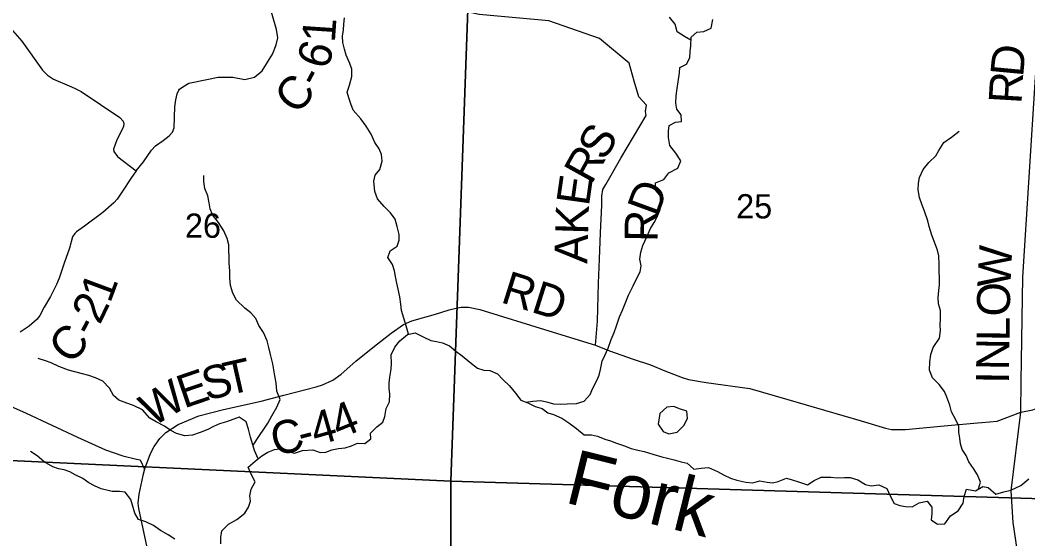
# Model space of a CAD drawing. Extents: x 2043100 to 2470832, y 443715 to 810583.
# Drawn here: x 2249519 to 2258688, y 675442 to 680160 of the extents above; entities that cross this region are included whole.
import ezdxf

# ---------------------------------------------------------------- set-up
doc = ezdxf.new("R2010")
doc.units = 0
for name, color, linetype in [('GM_X_County_Road', 7, 'Continuous'), ('GM_X_County_Road_Text', 7, 'Continuous'), ('GM_X_Minor_Lake', 7, 'Continuous'), ('GM_X_Minor_River', 7, 'Continuous'), ('GM_X_Minor_River_Text', 7, 'Continuous'), ('GM_X_Section', 7, 'Continuous'), ('GM_X_Section_Text', 7, 'Continuous'), ('GM_X_Township_Road', 7, 'Continuous'), ('GM_X_Township_Road_Text', 7, 'Continuous'), ('GM_X_Township_ROW', 7, 'Continuous')]:
    doc.layers.add(name, color=color, linetype=linetype)

msp = doc.modelspace()

# ---------------------------------------------------------------- linework, layer by layer
at = {"layer": 'GM_X_County_Road'}
for points in [[(2250963.1, 679521.8), (2250963.5, 679522.9), (2250967.9, 679532.7), (2250999.8, 679555), (2251053.7, 679585.4), (2251217.6, 679620.6), (2251321.7, 679641.4), (2251453.9, 679640.3), (2251562.2, 679619.1), (2251650.1, 679641.7), (2251721.8, 679700.3), (2251814.9, 679851.3), (2251848.3, 679935.7), (2251863.9, 679999.9), (2251851.3, 680075.9), (2251779.4, 680325.9)], [(2249449.9, 680065.1), (2249532.7, 679967.5), (2249720.8, 679706.3), (2249767.3, 679658.6), (2249821.6, 679622.9), (2249964.2, 679561.8), (2250014.5, 679540.1), (2250072.8, 679510.4), (2250425, 679274.5), (2250455.2, 679242.6), (2250463.4, 679218.6), (2250459.6, 679192.5), (2250394.5, 679061.8), (2250366.9, 678987.5), (2250371.1, 678965.5), (2250403.5, 678919.6), (2250405.4, 678918.2)], [(2250574.7, 678790.6), (2250640.2, 678871.2), (2250715.5, 678977.9), (2250751.3, 679018.3), (2250821.1, 679064.8), (2250874.8, 679107.3), (2250904.6, 679141.6), (2250920.4, 679181.7), (2250927, 679372.2), (2250934.6, 679436.3), (2250948.2, 679488.5), (2250963.1, 679521.8)], [(2250405.4, 678918.2), (2250407.7, 678916.5), (2250574.7, 678790.6), (2250527.1, 678720.1), (2250449.8, 678603.4), (2250402.3, 678532.9), (2250372.5, 678498.6), (2250271, 678409.7), (2250103.6, 678286.3), (2250031.9, 678235.7), (2250016, 678219.6), (2249996.1, 678189.4), (2249966.8, 678087), (2249917.8, 677950.4), (2249872.7, 677813.8), (2249849.1, 677755.6), (2249795.8, 677647), (2249738.4, 677550.4), (2249696.9, 677471.9), (2249673.1, 677439.7), (2249601.4, 677375.1), (2249517.7, 677322.4)], [(2250650.3, 676074), (2250675.9, 676136.3), (2250705.4, 676218.6), (2250737, 676281), (2250790.5, 676355.5), (2250844.2, 676410), (2250955.8, 676480.9), (2251145.5, 676560.4), (2251369.5, 676618), (2251711.4, 676694.6), (2251917.3, 676750.1), (2252211.2, 676824.3), (2252269.2, 676842.7), (2252365, 676885.5), (2252440.7, 676940.1), (2252574.1, 677057.3), (2252743.3, 677194.7), (2252894.7, 677314), (2253008.3, 677393), (2253084.2, 677423.5), (2253298.1, 677485.2), (2253422, 677524.1), (2253485.9, 677540.6), (2253531.9, 677548.9), (2253598, 677549.4), (2253700.3, 677528), (2254330.7, 677334.1), (2254754.2, 677202.8), (2254882.8, 677151.6), (2255097.6, 677077), (2255254.3, 677024), (2255384.8, 676970.8), (2255541.5, 676909.8), (2255601.7, 676890.1), (2255760.1, 676865.2), (2256157.1, 676807.9), (2256504.3, 676710.1), (2257170.7, 676514.4), (2257393.6, 676447.8), (2257447.7, 676436.2), (2257575.9, 676437.1), (2257928.2, 676469.6), (2258231, 676497), (2258270.4, 676500.6)], [(2258270.4, 676500.6), (2258408.6, 676513.1), (2258624.2, 676592.6), (2258734.2, 676614), (2258825.8, 676651), (2259069.4, 676789.4), (2259231.2, 676853.7), (2259352, 676914.1), (2259428, 676935.6), (2259535.2, 676939.5), (2259644.3, 676935.6), (2259697, 676943.4), (2259780.8, 676980.4), (2259885.3, 676994.3), (2259933.1, 677038.8), (2259974.8, 677083.1), (2260030.5, 677131.6), (2260158.1, 677212.7), (2260247.9, 677259.4), (2260321.9, 677282), (2260388, 677284.4), (2260486.2, 677277.1), (2260688.5, 677272.5), (2260794.6, 677279.3)], [(2249376.1, 676674.2), (2249573.1, 676583.4), (2250041.3, 676366.3), (2250294.5, 676251.8), (2250453.1, 676196.8), (2250577.5, 676167.6), (2250611.6, 676159.9), (2250650.3, 676074), (2250634.7, 676017.7), (2250597.9, 675849.2), (2250590.4, 675767), (2250596.8, 675718.9), (2250634.2, 675532.8), (2250667.4, 675376.8)]]:
    msp.add_lwpolyline(points, dxfattribs=at)
at = {"layer": 'GM_X_Minor_Lake'}
for points in [[(2255588.5, 676573.5), (2255586.5, 676602), (2255518.2, 676625.3), (2255468, 676646.8), (2255404.1, 676640.2), (2255340.8, 676581.4), (2255323.7, 676485.2)], [(2255323.7, 676485.2), (2255368.4, 676419.5), (2255420.6, 676396), (2255496.4, 676412.8), (2255557.8, 676471.5), (2255591.1, 676535.9), (2255588.5, 676573.5)]]:
    msp.add_lwpolyline(points, dxfattribs=at)
at = {"layer": 'GM_X_Minor_River'}
for points in [[(2255622.6, 679977.2), (2255563.6, 680011.5), (2255497.2, 680052.9), (2255478.5, 680122.8), (2255427.8, 680188.3)], [(2253053.3, 677303.4), (2253031.4, 677379), (2253008.7, 677448.8), (2252988, 677518.7), (2252981.4, 677576.7), (2252972.7, 677642.7), (2252958, 677712.6), (2252947.5, 677766.6), (2252932.8, 677828.5), (2252924.3, 677880.5), (2252905.7, 677938.4), (2252863.1, 678000), (2252886.5, 678060.3), (2252950, 678105), (2252967.4, 678159.2), (2252966.9, 678211.3), (2252950.2, 678283.2), (2252931.5, 678351.1), (2252888.9, 678408.7), (2252830.4, 678464.2), (2252771.7, 678535.7), (2252747, 678601.5), (2252736, 678695.5), (2252749.5, 678749.7), (2252790.9, 678802.2), (2252814.1, 678878.5), (2252807.5, 678936.5), (2252787, 678988.3), (2252746.5, 679046), (2252713.7, 679121.7), (2252666.9, 679195.3), (2252618.3, 679262.9), (2252549.5, 679340.3), (2252526.9, 679398.2), (2252508.4, 679452), (2252493.9, 679503.9), (2252515.2, 679570.2), (2252538.4, 679646.6), (2252537.7, 679714.6), (2252519.2, 679766.5), (2252486.4, 679842.2), (2252469.9, 679896.1), (2252455.2, 679958.1), (2252452.7, 680014.1), (2252460.1, 680072.2), (2252465.5, 680124.4), (2252468.9, 680180.4)], [(2254117.7, 676685.8), (2254185.1, 676693.1), (2254255.9, 676700.6), (2254320, 676685.2), (2254372.2, 676669.8), (2254438.2, 676666.4), (2254496.1, 676671), (2254580.1, 676671.9), (2254649.9, 676692.6), (2254705.2, 676755.2), (2254728.6, 676813.5), (2254763.9, 676875.9), (2254787.4, 676930.2), (2254798.8, 676982.4), (2254814.1, 677056.7), (2254839.5, 677109), (2254868.8, 677175.3), (2254896, 677253.7), (2254923.4, 677318), (2254944.7, 677380.3), (2254971.9, 677462.7), (2254999.3, 677521), (2255024.6, 677583.4), (2255055.8, 677659.8), (2255097, 677742.3), (2255130.2, 677812.7), (2255161.6, 677871.1), (2255169.1, 677925.2), (2255156.5, 677985.2), (2255167.8, 678049.3), (2255185.2, 678109.6), (2255220.3, 678190), (2255253.6, 678264.4), (2255289, 678320.9), (2255314.5, 678371.2), (2255343.8, 678437.5), (2255353.2, 678491.7), (2255348.6, 678555.7), (2255297.9, 678619.3), (2255301.3, 678681.4), (2255375, 678710.2), (2255420.3, 678772.7), (2255501.9, 678813.6), (2255529.2, 678879.9), (2255486.5, 678951.6), (2255429.8, 679021.1), (2255419, 679093), (2255418.5, 679151.1), (2255425.9, 679201.2), (2255481.6, 679231.8), (2255535.5, 679238.4), (2255534.9, 679298.4), (2255494.4, 679350.1), (2255485.8, 679404.1), (2255487.2, 679470.2), (2255496.5, 679538.3), (2255505.8, 679600.5), (2255519, 679680.7), (2255522.5, 679730.8), (2255582.2, 679759.4), (2255611.6, 679817.8), (2255617, 679875.9), (2255620.5, 679926), (2255623.7, 680004.1), (2255677.2, 680050.7), (2255741.1, 680057.4), (2255806.7, 680088.1), (2255821.9, 680166.3)], [(2258239.3, 675895.1), (2258256.1, 675958.2), (2258229.5, 676024), (2258192.9, 676081.7), (2258152.3, 676143.4), (2258125.7, 676201.2), (2258091.2, 676252.9), (2258076.6, 676306.8), (2258068.1, 676358.8), (2258061.6, 676410.8), (2258061, 676466.8), (2258032.4, 676524.6), (2257993.7, 676596.3), (2257977.1, 676656.2), (2257952.3, 676730), (2257929.8, 676781.8), (2257881.2, 676845.4), (2257820.6, 676906.9), (2257793.9, 676974.7), (2257795.1, 677050.8), (2257804.4, 677119), (2257825.8, 677183.2), (2257882.9, 677265.9), (2257894.2, 677336.1), (2257889.7, 677386.1), (2257893.1, 677444.2), (2257892.3, 677520.3), (2257873.7, 677580.2), (2257873.1, 677636.2), (2257878.4, 677700.3), (2257883.9, 677752.5), (2257882, 677938.7), (2257877.2, 678014.7), (2257866.7, 678068.6), (2257838, 678140.4), (2257813.3, 678204.2), (2257790.5, 678282.1), (2257778, 678336), (2257749.1, 678421.8), (2257726.6, 678475.7), (2257701.8, 678547.5), (2257691.1, 678617.5), (2257694.5, 678677.6), (2257702, 678727.7), (2257735.2, 678802.1), (2257786.6, 678864.7), (2257851.9, 678925.4), (2257879.4, 678975.8), (2257922.7, 679046.3), (2257992.1, 679095), (2258063.6, 679149.8)], [(2251637.7, 676294.8), (2251696, 676382.4), (2251735.4, 676438.8), (2251772.9, 676495.3), (2251810.2, 676561.8), (2251853.4, 676638.3), (2251884.6, 676708.7), (2251853.9, 676786.4), (2251847.1, 676860.4), (2251836.5, 676924.4), (2251827.9, 676978.4), (2251817.3, 677034.3), (2251796.5, 677118.2), (2251781.8, 677182.2), (2251767.2, 677244.1), (2251732.5, 677317.8), (2251689.8, 677381.4), (2251663.2, 677445.2), (2251618.6, 677498.9), (2251564.2, 677540.4), (2251487.5, 677613.7), (2251452.9, 677675.4), (2251432.2, 677747.2), (2251427.5, 677817.3), (2251426.8, 677877.3), (2251422.1, 677953.4), (2251421.5, 678007.4), (2251418.9, 678065.5), (2251416.4, 678115.5), (2251401.8, 678173.4), (2251373.1, 678243.2), (2251322.3, 678320.8), (2251269.7, 678388.3), (2251247.1, 678444.2), (2251238.6, 678498.1), (2251225.9, 678562.1), (2251199.2, 678629.9), (2251190.6, 678691.9), (2251190, 678747.9)], [(2251344.2, 675397.7), (2251343.7, 675453.8), (2251355, 675514), (2251414.4, 675576.6), (2251489.9, 675617.4), (2251563.3, 675676.3), (2251596.7, 675730.7), (2251614.2, 675782.9), (2251609.7, 675832.9), (2251621.1, 675893.1), (2251656.4, 675959.5), (2251623.7, 676025.3), (2251593, 676095), (2251656.5, 676147.7), (2251717.9, 676196.4), (2251771.6, 676231), (2251833.3, 676255.6), (2251907.2, 676262.4), (2251963.5, 676232.9), (2252015.6, 676221.4), (2252089.3, 676244.2), (2252181.2, 676251.2), (2252247.4, 676227.8), (2252299.4, 676230.3), (2252355.2, 676250.9), (2252417, 676263.5), (2252476.9, 676268.2), (2252532.7, 676288.7), (2252588.4, 676313.3), (2252654.5, 676308), (2252710, 676350.6), (2252707.5, 676402.6), (2252762.9, 676459.3), (2252820.4, 676503.9), (2252835.9, 676556.1), (2252849.1, 676628.3), (2252878.5, 676688.7), (2252881.8, 676756.8), (2252875.3, 676808.8), (2252876.8, 676858.9), (2252882.2, 676911), (2252893.5, 676985.2), (2252896.9, 677035.3), (2252896.1, 677115.3), (2252927.4, 677185.7), (2252972.8, 677244.3), (2253042.2, 677301), (2253112, 677315.7), (2253186.4, 677278.5), (2253256.7, 677247.1)], [(2253256.7, 677247.1), (2253306.8, 677235.6), (2253362.8, 677226.2), (2253425.1, 677196.8), (2253483.6, 677149.3), (2253540, 677107.8), (2253610.6, 677048.5), (2253681.1, 676993.1), (2253739.3, 676975.7), (2253791.3, 676972.2), (2253863.6, 676942.9), (2253910.1, 676891.3), (2253970.6, 676833.9), (2254027.3, 676766.4), (2254075.9, 676702.8), (2254138.2, 676677.4), (2254204.5, 676646), (2254268.6, 676628.7), (2254321, 676587.2), (2254371.2, 676571.6), (2254447.5, 676540.4), (2254511.9, 676497), (2254580.4, 676445.6), (2254651, 676386.3), (2254719, 676386.9), (2254773, 676375.5), (2254839.3, 676348.1), (2254891.4, 676334.6), (2254945.6, 676311.2), (2255009.8, 676289.8), (2255078.1, 676262.4), (2255140.2, 676249), (2255196.3, 676235.6), (2255274.5, 676212.4), (2255358.8, 676187.2), (2255408.9, 676175.7), (2255469, 676160.3), (2255533.2, 676140.9), (2255587.3, 676131.4), (2255647.8, 676076), (2255715.7, 676084.7), (2255781.6, 676091.4), (2255864, 676054.2), (2255918.2, 676024.7), (2255982.5, 675993.3), (2256040.7, 675975.8), (2256120.9, 675956.6), (2256186.9, 675951.3), (2256248.7, 675969.9), (2256314.8, 675956.6), (2256364.8, 675951.1), (2256416.7, 675963.6), (2256492.4, 675992.4), (2256542.5, 675978.9), (2256600.7, 675959.5), (2256682.9, 675932.3), (2256742.5, 675970.9), (2256808.2, 676001.6), (2256896.1, 676002.5), (2256952.2, 675997.1), (2257020.1, 675999.8), (2257070.1, 675998.3), (2257142.3, 675977), (2257210.7, 675935.6), (2257262.8, 675924.2), (2257332.7, 675932.9), (2257405, 675899.6), (2257435.7, 675831.8), (2257472.4, 675762.1), (2257524.6, 675744.6), (2257574.6, 675737.1), (2257636.6, 675733.7), (2257700.3, 675768.4), (2257772.1, 675785.1), (2257814.6, 675729.5), (2257813.2, 675669.4), (2257807.8, 675613.3), (2257866.2, 675575.9), (2257934.1, 675578.5), (2257985.4, 675651.2), (2258054.9, 675697.9), (2258100.1, 675766.4), (2258107.5, 675826.6), (2258128.8, 675894.9), (2258210.9, 675879.7), (2258278.6, 675916.4), (2258328.6, 675908.9), (2258397.2, 675849.5), (2258471, 675868.3), (2258534.8, 675883), (2258624.3, 675927.9), (2258697.7, 675986.7)], [(2251684.1, 676169.6), (2251651.5, 676243.8), (2251636.9, 676297.7), (2251614.2, 676367.5), (2251595.5, 676439.4), (2251576.8, 676507.3), (2251512.4, 676548.7), (2251454.7, 676526.1), (2251396.9, 676507.5), (2251333.1, 676488.8), (2251277.4, 676462.3), (2251225.6, 676437.7), (2251156, 676409), (2251086.2, 676386.2), (2251016.3, 676377.5), (2250942.1, 676400.8), (2250889.8, 676428.3), (2250831.5, 676467.8), (2250755.1, 676505), (2250698.8, 676540.5), (2250632, 676613.9), (2250551.6, 676655.1), (2250489.5, 676674.5), (2250417.2, 676703.8), (2250366.8, 676745.4), (2250332.1, 676811.1), (2250271.5, 676874.5), (2250203.2, 676905.9), (2250143, 676927.3), (2250074.8, 676946.6), (2250016.7, 676962.1), (2249958.6, 676975.5), (2249872.2, 677010.7), (2249801.9, 677042), (2249749.8, 677059.5), (2249681.6, 677080.8)], [(2250925.9, 675439.5), (2250865.6, 675479), (2250795.2, 675516.3), (2250732.8, 675561.7), (2250662.4, 675595.1), (2250596.2, 675618.4), (2250563.7, 675674.2), (2250540.9, 675748), (2250526.4, 675799.9), (2250475.7, 675867.5), (2250423.7, 675871), (2250355.7, 675872.3), (2250255.5, 675895.3), (2250195.3, 675922.7), (2250143, 675952.2), (2250088.6, 675989.7), (2250020.3, 676023.1), (2249970, 676052.6), (2249917.9, 676068.1), (2249867.8, 676079.6), (2249815.6, 676097.1), (2249737.2, 676142.3), (2249674.6, 676195.8), (2249614.3, 676235.2)]]:
    msp.add_lwpolyline(points, dxfattribs=at)
at = {"layer": 'GM_X_Section'}
for points in [[(2248150.8, 681542), (2253630.3, 681270.6), (2253436.7, 675966.1), (2248002, 676220.2)], [(2253630.3, 681270.6), (2258920.6, 681100.8), (2258826.9, 675805.5), (2253436.7, 675966.1)], [(2248002, 676220.2), (2253436.7, 675966.1), (2253429.7, 670607.7), (2248097.4, 670695), (2247901.2, 670696.9)], [(2258826.9, 675805.5), (2258713.1, 670509.8), (2253429.7, 670607.7), (2253436.7, 675966.1)]]:
    msp.add_lwpolyline(points, close=True, dxfattribs=at)
at = {"layer": 'GM_X_Township_Road'}
for points in [[(2258624.2, 676592.6), (2258628.3, 676873.3), (2258643.5, 677823.2), (2258756.6, 679641.4), (2258814, 680295), (2258780.8, 680447.1), (2258692.3, 680508.6), (2258583.7, 680559.9), (2258463.3, 680599.1), (2258419.1, 680618.9), (2258396.4, 680631.2), (2258382.9, 680638.6), (2258381.1, 680657.1)], [(2254754.2, 677202.8), (2254773.2, 677420.5), (2254782.8, 677767), (2254791.3, 677985.3), (2254799.7, 678225.7), (2254811.9, 678478.1), (2254811.3, 678558.2), (2254820.9, 678618.4), (2254848.6, 678664.6), (2254985, 678903.9), (2255216.3, 679292), (2255210, 679330), (2255219.6, 679388.1), (2255147.1, 679463.7), (2255106.1, 679605.1), (2255105.7, 679606.5)]]:
    msp.add_lwpolyline(points, dxfattribs=at)
at = {"layer": 'GM_X_Township_ROW'}
for points in [[(2255105.7, 679606.5), (2255059, 679767.5), (2254789.4, 679992), (2254330.2, 680155), (2253695.8, 680210.8), (2253513.5, 680251.6), (2253421.5, 680535.3), (2253410.2, 682151.1)], [(2257200.8, 671983.3), (2257201.6, 671984.8), (2257436, 672507.5), (2257724.5, 673012.2), (2258103, 673534.9), (2258445.6, 674021.5), (2258625.9, 674652.3), (2258643.9, 674994.8), (2258553.8, 675589.6), (2258535.8, 675878), (2258624.2, 676592.6)]]:
    msp.add_lwpolyline(points, dxfattribs=at)

# ---------------------------------------------------------------- texts
at = {"layer": 'GM_X_County_Road_Text'}
for s, rotation, p in [('1', 86.12887, (2252382.1, 679950.8)), ('6', 73.18366, (2252315.4, 679701.3)), ('C', 50.43378, (2252039.5, 679288.7)), ('-', 61.95408, (2252233, 679533.3)), ('1', 69.64322, (2250337.5, 677578)), ('RD', 342.49922, (2253881.4, 677596.5)), ('2', 63.873, (2250243.1, 677381.8)), ('C', 49.39235, (2249980.4, 677016.4)), ('-', 62.51976, (2250182.7, 677265.5)), ('T', 12.75658, (2251409, 676745.8)), ('E', 18.87403, (2251008.6, 676625.9)), ('S', 14.19988, (2251214.7, 676696.7)), ('W', 30.53007, (2250723.8, 676456.1)), ('4', 15.97413, (2252208.9, 676285.7)), ('4', 22.07135, (2252419.5, 676347.9)), ('C', 14.42153, (2251842.6, 676190.6)), ('-', 14.74115, (2252083, 676252.4))]:
    msp.add_text(s, height=300, rotation=rotation, dxfattribs=at).set_placement(p)
at = {"layer": 'GM_X_Minor_River_Text'}
msp.add_text('Fork', height=499.98, rotation=346.11704, dxfattribs=at).set_placement((2254461, 675774.9))
at = {"layer": 'GM_X_Section_Text'}
for s, p in [('25', (2256033.8, 678356.3)), ('26', (2251017.8, 678180.3))]:
    msp.add_text(s, height=220.83, rotation=0.00001, dxfattribs=at).set_placement(p)
at = {"layer": 'GM_X_Township_Road_Text'}
for s, rotation, p in [('D', 84.65913, (2258644.4, 679636.9)), ('R', 86.59847, (2258630, 679393.6)), ('S', 59.62214, (2254834.8, 678870.3)), ('R', 60.92416, (2254715.9, 678656.5)), ('E', 81.91171, (2254693.6, 678461.7)), ('D', 69.88991, (2255317.8, 678361.5)), ('K', 88.25116, (2254686.3, 678206.6)), ('R', 88.7822, (2255317.4, 678140.7)), ('A', 88.35686, (2254678.7, 677942.8)), ('W', 87.07983, (2258528.2, 677723.6)), ('O', 89.03095, (2258523.8, 677462.3)), ('L', 89.22513, (2258520.8, 677238.2)), ('N', 89.22405, (2258517.2, 676974.2)), ('I', 89.22714, (2258515.5, 676851))]:
    msp.add_text(s, height=300, rotation=rotation, dxfattribs=at).set_placement(p)

doc.saveas('drawing.dxf')
